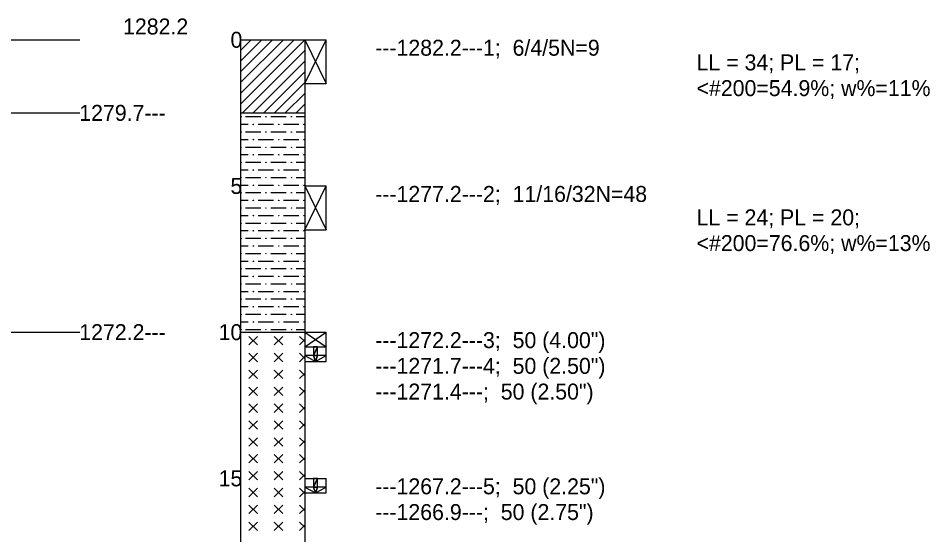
# Model space of a CAD drawing. Extents: x 2150161.5 to 2150203.1, y 143779.5 to 143868.5.
# Drawn here: x 2150174.63 to 2150181.72, y 143825.26 to 143829.28 of the extents above; entities that cross this region are included whole.
import ezdxf

# ---------------------------------------------------------------- set-up
doc = ezdxf.new("R2010")
doc.units = 0
doc.layers.add('Default', color=7, linetype='Continuous')

msp = doc.modelspace()

# ---------------------------------------------------------------- linework, layer by layer
at = {"layer": 'Default'}
for points in [[(2150170.9397, 143829.1095), (2150175.1064, 143829.1095)], [(2150176.3564, 143829.0262), (2150176.4397, 143829.1095)], [(2150176.3564, 143828.9428), (2150176.523, 143829.1095)], [(2150176.3564, 143828.8595), (2150176.6064, 143829.1095)], [(2150176.3564, 143828.7762), (2150176.6897, 143829.1095)], [(2150176.3564, 143828.6928), (2150176.773, 143829.1095)], [(2150176.3564, 143828.6095), (2150176.8564, 143829.1095)], [(2150176.3564, 143829.1095), (2150176.3564, 143816.9504)], [(2150176.3564, 143829.1095), (2150176.8564, 143829.1095)], [(2150176.8564, 143829.1095), (2150177.023, 143828.7686)], [(2150176.8564, 143828.7686), (2150177.023, 143829.1095)], [(2150176.8564, 143829.1095), (2150177.023, 143829.1095)], [(2150176.8564, 143829.1095), (2150176.8564, 143816.9504)], [(2150177.023, 143828.7686), (2150177.023, 143829.1095)], [(2150176.3715, 143828.5413), (2150176.8564, 143829.0262)], [(2150176.4548, 143828.5413), (2150176.8564, 143828.9428)], [(2150176.5382, 143828.5413), (2150176.8564, 143828.8595)], [(2150176.6215, 143828.5413), (2150176.8564, 143828.7762)], [(2150176.8564, 143828.7686), (2150177.023, 143828.7686)], [(2150176.7048, 143828.5413), (2150176.8564, 143828.6928)], [(2150176.7882, 143828.5413), (2150176.8564, 143828.6095)], [(2150170.9397, 143828.5413), (2150175.1064, 143828.5413)], [(2150176.3564, 143828.5413), (2150176.8564, 143828.5413)], [(2150176.3564, 143828.5118), (2150176.3603, 143828.5118), (2150176.3603, 143828.5079), (2150176.3564, 143828.5118)], [(2150176.3957, 143828.5118), (2150176.5138, 143828.5118)], [(2150176.5532, 143828.5118), (2150176.5571, 143828.5118), (2150176.5532, 143828.5079), (2150176.5532, 143828.5118)], [(2150176.5926, 143828.5118), (2150176.7107, 143828.5118)], [(2150176.7501, 143828.5118), (2150176.754, 143828.5118), (2150176.754, 143828.5079), (2150176.7501, 143828.5118)], [(2150176.7894, 143828.5118), (2150176.8564, 143828.5118)], [(2150176.3564, 143828.4527), (2150176.4154, 143828.4527)], [(2150176.4548, 143828.4527), (2150176.4587, 143828.4527), (2150176.4548, 143828.4488), (2150176.4548, 143828.4527)], [(2150176.4942, 143828.4527), (2150176.6123, 143828.4527)], [(2150176.6516, 143828.4527), (2150176.6556, 143828.4527), (2150176.6556, 143828.4488), (2150176.6516, 143828.4527)], [(2150176.691, 143828.4527), (2150176.7501, 143828.4527)], [(2150176.7501, 143828.4527), (2150176.8091, 143828.4527)], [(2150176.8485, 143828.4527), (2150176.8524, 143828.4527), (2150176.8485, 143828.4488), (2150176.8485, 143828.4527)], [(2150176.3564, 143828.3937), (2150176.3603, 143828.3937), (2150176.3603, 143828.3898), (2150176.3564, 143828.3937)], [(2150176.3957, 143828.3937), (2150176.5138, 143828.3937)], [(2150176.5532, 143828.3937), (2150176.5571, 143828.3937), (2150176.5532, 143828.3898), (2150176.5532, 143828.3937)], [(2150176.5926, 143828.3937), (2150176.7107, 143828.3937)], [(2150176.7501, 143828.3937), (2150176.754, 143828.3937), (2150176.754, 143828.3898), (2150176.7501, 143828.3937)], [(2150176.7894, 143828.3937), (2150176.8564, 143828.3937)], [(2150176.3564, 143828.3346), (2150176.4154, 143828.3346)], [(2150176.4548, 143828.3346), (2150176.4587, 143828.3346), (2150176.4548, 143828.3307), (2150176.4548, 143828.3346)], [(2150176.4942, 143828.3346), (2150176.6123, 143828.3346)], [(2150176.6516, 143828.3346), (2150176.6556, 143828.3346), (2150176.6556, 143828.3307), (2150176.6516, 143828.3346)], [(2150176.691, 143828.3346), (2150176.7501, 143828.3346)], [(2150176.7501, 143828.3346), (2150176.8091, 143828.3346)], [(2150176.8485, 143828.3346), (2150176.8524, 143828.3346), (2150176.8485, 143828.3307), (2150176.8485, 143828.3346)], [(2150176.3564, 143828.2756), (2150176.3603, 143828.2756), (2150176.3603, 143828.2716), (2150176.3564, 143828.2756)], [(2150176.3564, 143828.2165), (2150176.4154, 143828.2165)], [(2150176.3957, 143828.2756), (2150176.5138, 143828.2756)], [(2150176.4548, 143828.2165), (2150176.4587, 143828.2165), (2150176.4548, 143828.2126), (2150176.4548, 143828.2165)], [(2150176.4942, 143828.2165), (2150176.6123, 143828.2165)], [(2150176.5532, 143828.2756), (2150176.5571, 143828.2756), (2150176.5532, 143828.2716), (2150176.5532, 143828.2756)], [(2150176.5926, 143828.2756), (2150176.7107, 143828.2756)], [(2150176.6516, 143828.2165), (2150176.6556, 143828.2165), (2150176.6556, 143828.2126), (2150176.6516, 143828.2165)], [(2150176.691, 143828.2165), (2150176.7501, 143828.2165)], [(2150176.7501, 143828.2756), (2150176.754, 143828.2756), (2150176.754, 143828.2716), (2150176.7501, 143828.2756)], [(2150176.7501, 143828.2165), (2150176.8091, 143828.2165)], [(2150176.7894, 143828.2756), (2150176.8564, 143828.2756)], [(2150176.8485, 143828.2165), (2150176.8524, 143828.2165), (2150176.8485, 143828.2126), (2150176.8485, 143828.2165)], [(2150176.3564, 143828.1575), (2150176.3603, 143828.1575), (2150176.3603, 143828.1535), (2150176.3564, 143828.1575)], [(2150176.3957, 143828.1575), (2150176.5138, 143828.1575)], [(2150176.5532, 143828.1575), (2150176.5571, 143828.1575), (2150176.5532, 143828.1535), (2150176.5532, 143828.1575)], [(2150176.5926, 143828.1575), (2150176.7107, 143828.1575)], [(2150176.7501, 143828.1575), (2150176.754, 143828.1575), (2150176.754, 143828.1535), (2150176.7501, 143828.1575)], [(2150176.7894, 143828.1575), (2150176.8564, 143828.1575)], [(2150176.3564, 143828.0984), (2150176.4154, 143828.0984)], [(2150176.4548, 143828.0984), (2150176.4587, 143828.0984), (2150176.4548, 143828.0945), (2150176.4548, 143828.0984)], [(2150176.4942, 143828.0984), (2150176.6123, 143828.0984)], [(2150176.6516, 143828.0984), (2150176.6556, 143828.0984), (2150176.6556, 143828.0945), (2150176.6516, 143828.0984)], [(2150176.691, 143828.0984), (2150176.7501, 143828.0984)], [(2150176.7501, 143828.0984), (2150176.8091, 143828.0984)], [(2150176.8485, 143828.0984), (2150176.8524, 143828.0984), (2150176.8485, 143828.0945), (2150176.8485, 143828.0984)], [(2150176.3564, 143828.0394), (2150176.3603, 143828.0394), (2150176.3603, 143828.0354), (2150176.3564, 143828.0394)], [(2150176.3957, 143828.0394), (2150176.5138, 143828.0394)], [(2150176.5532, 143828.0394), (2150176.5571, 143828.0394), (2150176.5532, 143828.0354), (2150176.5532, 143828.0394)], [(2150176.5926, 143828.0394), (2150176.7107, 143828.0394)], [(2150176.7501, 143828.0394), (2150176.754, 143828.0394), (2150176.754, 143828.0354), (2150176.7501, 143828.0394)], [(2150176.7894, 143828.0394), (2150176.8564, 143828.0394)], [(2150176.3564, 143827.9803), (2150176.4154, 143827.9803)], [(2150176.4548, 143827.9803), (2150176.4587, 143827.9803), (2150176.4548, 143827.9764), (2150176.4548, 143827.9803)], [(2150176.4942, 143827.9803), (2150176.6123, 143827.9803)], [(2150176.6516, 143827.9803), (2150176.6556, 143827.9803), (2150176.6556, 143827.9764), (2150176.6516, 143827.9803)], [(2150176.691, 143827.9803), (2150176.7501, 143827.9803)], [(2150176.7501, 143827.9803), (2150176.8091, 143827.9803)], [(2150176.8485, 143827.9803), (2150176.8524, 143827.9803), (2150176.8485, 143827.9764), (2150176.8485, 143827.9803)], [(2150176.8564, 143827.9731), (2150177.023, 143827.6322)], [(2150176.8564, 143827.6322), (2150177.023, 143827.9731)], [(2150176.8564, 143827.9731), (2150177.023, 143827.9731)], [(2150177.023, 143827.6322), (2150177.023, 143827.9731)], [(2150176.3564, 143827.9212), (2150176.3603, 143827.9212), (2150176.3603, 143827.9173), (2150176.3564, 143827.9212)], [(2150176.3564, 143827.8622), (2150176.4154, 143827.8622)], [(2150176.3957, 143827.9212), (2150176.5138, 143827.9212)], [(2150176.4548, 143827.8622), (2150176.4587, 143827.8622), (2150176.4548, 143827.8583), (2150176.4548, 143827.8622)], [(2150176.4942, 143827.8622), (2150176.6123, 143827.8622)], [(2150176.5532, 143827.9212), (2150176.5571, 143827.9212), (2150176.5532, 143827.9173), (2150176.5532, 143827.9212)], [(2150176.5926, 143827.9212), (2150176.7107, 143827.9212)], [(2150176.6516, 143827.8622), (2150176.6556, 143827.8622), (2150176.6556, 143827.8583), (2150176.6516, 143827.8622)], [(2150176.691, 143827.8622), (2150176.7501, 143827.8622)], [(2150176.7501, 143827.9212), (2150176.754, 143827.9212), (2150176.754, 143827.9173), (2150176.7501, 143827.9212)], [(2150176.7501, 143827.8622), (2150176.8091, 143827.8622)], [(2150176.7894, 143827.9212), (2150176.8564, 143827.9212)], [(2150176.8485, 143827.8622), (2150176.8524, 143827.8622), (2150176.8485, 143827.8583), (2150176.8485, 143827.8622)], [(2150176.3564, 143827.8031), (2150176.3603, 143827.8031), (2150176.3603, 143827.7992), (2150176.3564, 143827.8031)], [(2150176.3957, 143827.8031), (2150176.5138, 143827.8031)], [(2150176.5532, 143827.8031), (2150176.5571, 143827.8031), (2150176.5532, 143827.7992), (2150176.5532, 143827.8031)], [(2150176.5926, 143827.8031), (2150176.7107, 143827.8031)], [(2150176.7501, 143827.8031), (2150176.754, 143827.8031), (2150176.754, 143827.7992), (2150176.7501, 143827.8031)], [(2150176.7894, 143827.8031), (2150176.8564, 143827.8031)], [(2150176.3564, 143827.7441), (2150176.4154, 143827.7441)], [(2150176.4548, 143827.7441), (2150176.4587, 143827.7441), (2150176.4548, 143827.7401), (2150176.4548, 143827.7441)], [(2150176.4942, 143827.7441), (2150176.6123, 143827.7441)], [(2150176.6516, 143827.7441), (2150176.6556, 143827.7441), (2150176.6556, 143827.7401), (2150176.6516, 143827.7441)], [(2150176.691, 143827.7441), (2150176.7501, 143827.7441)], [(2150176.7501, 143827.7441), (2150176.8091, 143827.7441)], [(2150176.8485, 143827.7441), (2150176.8524, 143827.7441), (2150176.8485, 143827.7401), (2150176.8485, 143827.7441)], [(2150176.3564, 143827.685), (2150176.3603, 143827.685), (2150176.3603, 143827.6811), (2150176.3564, 143827.685)], [(2150176.3957, 143827.685), (2150176.5138, 143827.685)], [(2150176.5532, 143827.685), (2150176.5571, 143827.685), (2150176.5532, 143827.6811), (2150176.5532, 143827.685)], [(2150176.5926, 143827.685), (2150176.7107, 143827.685)], [(2150176.7501, 143827.685), (2150176.754, 143827.685), (2150176.754, 143827.6811), (2150176.7501, 143827.685)], [(2150176.7894, 143827.685), (2150176.8564, 143827.685)], [(2150176.3564, 143827.626), (2150176.4154, 143827.626)], [(2150176.4548, 143827.626), (2150176.4587, 143827.626), (2150176.4548, 143827.622), (2150176.4548, 143827.626)], [(2150176.4942, 143827.626), (2150176.6123, 143827.626)], [(2150176.6516, 143827.626), (2150176.6556, 143827.626), (2150176.6556, 143827.622), (2150176.6516, 143827.626)], [(2150176.691, 143827.626), (2150176.7501, 143827.626)], [(2150176.7501, 143827.626), (2150176.8091, 143827.626)], [(2150176.8485, 143827.626), (2150176.8524, 143827.626), (2150176.8485, 143827.622), (2150176.8485, 143827.626)], [(2150176.8564, 143827.6322), (2150177.023, 143827.6322)], [(2150176.3564, 143827.5669), (2150176.3603, 143827.5669), (2150176.3603, 143827.563), (2150176.3564, 143827.5669)], [(2150176.3564, 143827.5079), (2150176.4154, 143827.5079)], [(2150176.3957, 143827.5669), (2150176.5138, 143827.5669)], [(2150176.4548, 143827.5079), (2150176.4587, 143827.5079), (2150176.4548, 143827.5039), (2150176.4548, 143827.5079)], [(2150176.4942, 143827.5079), (2150176.6123, 143827.5079)], [(2150176.5532, 143827.5669), (2150176.5571, 143827.5669), (2150176.5532, 143827.563), (2150176.5532, 143827.5669)], [(2150176.5926, 143827.5669), (2150176.7107, 143827.5669)], [(2150176.6516, 143827.5079), (2150176.6556, 143827.5079), (2150176.6556, 143827.5039), (2150176.6516, 143827.5079)], [(2150176.691, 143827.5079), (2150176.7501, 143827.5079)], [(2150176.7501, 143827.5669), (2150176.754, 143827.5669), (2150176.754, 143827.563), (2150176.7501, 143827.5669)], [(2150176.7501, 143827.5079), (2150176.8091, 143827.5079)], [(2150176.7894, 143827.5669), (2150176.8564, 143827.5669)], [(2150176.8485, 143827.5079), (2150176.8524, 143827.5079), (2150176.8485, 143827.5039), (2150176.8485, 143827.5079)], [(2150176.3564, 143827.4488), (2150176.3603, 143827.4488), (2150176.3603, 143827.4449), (2150176.3564, 143827.4488)], [(2150176.3957, 143827.4488), (2150176.5138, 143827.4488)], [(2150176.5532, 143827.4488), (2150176.5571, 143827.4488), (2150176.5532, 143827.4449), (2150176.5532, 143827.4488)], [(2150176.5926, 143827.4488), (2150176.7107, 143827.4488)], [(2150176.7501, 143827.4488), (2150176.754, 143827.4488), (2150176.754, 143827.4449), (2150176.7501, 143827.4488)], [(2150176.7894, 143827.4488), (2150176.8564, 143827.4488)], [(2150176.3564, 143827.3898), (2150176.4154, 143827.3898)], [(2150176.4548, 143827.3898), (2150176.4587, 143827.3898), (2150176.4548, 143827.3858), (2150176.4548, 143827.3898)], [(2150176.4942, 143827.3898), (2150176.6123, 143827.3898)], [(2150176.6516, 143827.3898), (2150176.6556, 143827.3898), (2150176.6556, 143827.3858), (2150176.6516, 143827.3898)], [(2150176.691, 143827.3898), (2150176.7501, 143827.3898)], [(2150176.7501, 143827.3898), (2150176.8091, 143827.3898)], [(2150176.8485, 143827.3898), (2150176.8524, 143827.3898), (2150176.8485, 143827.3858), (2150176.8485, 143827.3898)], [(2150176.3564, 143827.3307), (2150176.3603, 143827.3307), (2150176.3603, 143827.3268), (2150176.3564, 143827.3307)], [(2150176.3957, 143827.3307), (2150176.5138, 143827.3307)], [(2150176.5532, 143827.3307), (2150176.5571, 143827.3307), (2150176.5532, 143827.3268), (2150176.5532, 143827.3307)], [(2150176.5926, 143827.3307), (2150176.7107, 143827.3307)], [(2150176.7501, 143827.3307), (2150176.754, 143827.3307), (2150176.754, 143827.3268), (2150176.7501, 143827.3307)], [(2150176.7894, 143827.3307), (2150176.8564, 143827.3307)], [(2150176.3564, 143827.2716), (2150176.4154, 143827.2716)], [(2150176.4548, 143827.2716), (2150176.4587, 143827.2716), (2150176.4548, 143827.2677), (2150176.4548, 143827.2716)], [(2150176.4942, 143827.2716), (2150176.6123, 143827.2716)], [(2150176.6516, 143827.2716), (2150176.6556, 143827.2716), (2150176.6556, 143827.2677), (2150176.6516, 143827.2716)], [(2150176.691, 143827.2716), (2150176.7501, 143827.2716)], [(2150176.7501, 143827.2716), (2150176.8091, 143827.2716)], [(2150176.8485, 143827.2716), (2150176.8524, 143827.2716), (2150176.8485, 143827.2677), (2150176.8485, 143827.2716)], [(2150176.3564, 143827.2126), (2150176.3603, 143827.2126), (2150176.3603, 143827.2087), (2150176.3564, 143827.2126)], [(2150176.3564, 143827.1535), (2150176.4154, 143827.1535)], [(2150176.3957, 143827.2126), (2150176.5138, 143827.2126)], [(2150176.4548, 143827.1535), (2150176.4587, 143827.1535), (2150176.4548, 143827.1496), (2150176.4548, 143827.1535)], [(2150176.4942, 143827.1535), (2150176.6123, 143827.1535)], [(2150176.5532, 143827.2126), (2150176.5571, 143827.2126), (2150176.5532, 143827.2087), (2150176.5532, 143827.2126)], [(2150176.5926, 143827.2126), (2150176.7107, 143827.2126)], [(2150176.6516, 143827.1535), (2150176.6556, 143827.1535), (2150176.6556, 143827.1496), (2150176.6516, 143827.1535)], [(2150176.691, 143827.1535), (2150176.7501, 143827.1535)], [(2150176.7501, 143827.2126), (2150176.754, 143827.2126), (2150176.754, 143827.2087), (2150176.7501, 143827.2126)], [(2150176.7501, 143827.1535), (2150176.8091, 143827.1535)], [(2150176.7894, 143827.2126), (2150176.8564, 143827.2126)], [(2150176.8485, 143827.1535), (2150176.8524, 143827.1535), (2150176.8485, 143827.1496), (2150176.8485, 143827.1535)], [(2150176.3564, 143827.0945), (2150176.3603, 143827.0945), (2150176.3603, 143827.0905), (2150176.3564, 143827.0945)], [(2150176.3957, 143827.0945), (2150176.5138, 143827.0945)], [(2150176.5532, 143827.0945), (2150176.5571, 143827.0945), (2150176.5532, 143827.0905), (2150176.5532, 143827.0945)], [(2150176.5926, 143827.0945), (2150176.7107, 143827.0945)], [(2150176.7501, 143827.0945), (2150176.754, 143827.0945), (2150176.754, 143827.0905), (2150176.7501, 143827.0945)], [(2150176.7894, 143827.0945), (2150176.8564, 143827.0945)], [(2150176.3564, 143827.0354), (2150176.4154, 143827.0354)], [(2150176.4548, 143827.0354), (2150176.4587, 143827.0354), (2150176.4548, 143827.0315), (2150176.4548, 143827.0354)], [(2150176.4942, 143827.0354), (2150176.6123, 143827.0354)], [(2150176.6516, 143827.0354), (2150176.6556, 143827.0354), (2150176.6556, 143827.0315), (2150176.6516, 143827.0354)], [(2150176.691, 143827.0354), (2150176.7501, 143827.0354)], [(2150176.7501, 143827.0354), (2150176.8091, 143827.0354)], [(2150176.8485, 143827.0354), (2150176.8524, 143827.0354), (2150176.8485, 143827.0315), (2150176.8485, 143827.0354)], [(2150176.3564, 143826.9764), (2150176.3603, 143826.9764), (2150176.3603, 143826.9724), (2150176.3564, 143826.9764)], [(2150176.3957, 143826.9764), (2150176.5138, 143826.9764)], [(2150176.5532, 143826.9764), (2150176.5571, 143826.9764), (2150176.5532, 143826.9724), (2150176.5532, 143826.9764)], [(2150176.5926, 143826.9764), (2150176.7107, 143826.9764)], [(2150176.7501, 143826.9764), (2150176.754, 143826.9764), (2150176.754, 143826.9724), (2150176.7501, 143826.9764)], [(2150176.7894, 143826.9764), (2150176.8564, 143826.9764)], [(2150176.3564, 143826.9173), (2150176.4154, 143826.9173)], [(2150176.4548, 143826.9173), (2150176.4587, 143826.9173), (2150176.4548, 143826.9134), (2150176.4548, 143826.9173)], [(2150176.4942, 143826.9173), (2150176.6123, 143826.9173)], [(2150176.6516, 143826.9173), (2150176.6556, 143826.9173), (2150176.6556, 143826.9134), (2150176.6516, 143826.9173)], [(2150176.691, 143826.9173), (2150176.7501, 143826.9173)], [(2150176.7501, 143826.9173), (2150176.8091, 143826.9173)], [(2150176.8485, 143826.9173), (2150176.8524, 143826.9173), (2150176.8485, 143826.9134), (2150176.8485, 143826.9173)], [(2150170.9397, 143826.8368), (2150175.1064, 143826.8368)], [(2150176.3564, 143826.8583), (2150176.3603, 143826.8583), (2150176.3603, 143826.8543), (2150176.3564, 143826.8583)], [(2150176.3564, 143826.8368), (2150176.8564, 143826.8368)], [(2150176.3957, 143826.8583), (2150176.5138, 143826.8583)], [(2150176.4876, 143826.804), (2150176.422, 143826.7384)], [(2150176.422, 143826.804), (2150176.4876, 143826.7384)], [(2150176.5532, 143826.8583), (2150176.5571, 143826.8583), (2150176.5532, 143826.8543), (2150176.5532, 143826.8583)], [(2150176.5926, 143826.8583), (2150176.7107, 143826.8583)], [(2150176.6844, 143826.804), (2150176.6188, 143826.7384)], [(2150176.6188, 143826.804), (2150176.6844, 143826.7384)], [(2150176.7501, 143826.8583), (2150176.754, 143826.8583), (2150176.754, 143826.8543), (2150176.7501, 143826.8583)], [(2150176.7894, 143826.8583), (2150176.8564, 143826.8583)], [(2150176.8157, 143826.804), (2150176.8564, 143826.7633)], [(2150176.8564, 143826.8368), (2150177.023, 143826.7231)], [(2150176.8564, 143826.7231), (2150177.023, 143826.8368)], [(2150176.8564, 143826.8368), (2150177.023, 143826.8368)], [(2150177.023, 143826.7231), (2150177.023, 143826.8368)], [(2150176.8564, 143826.779), (2150176.8157, 143826.7384)], [(2150176.8564, 143826.7231), (2150177.023, 143826.7231)], [(2150176.8564, 143826.7231), (2150177.023, 143826.7231)], [(2150177.023, 143826.6095), (2150177.023, 143826.7231)], [(2150176.4876, 143826.6727), (2150176.422, 143826.6071)], [(2150176.422, 143826.6727), (2150176.4876, 143826.6071)], [(2150176.6844, 143826.6727), (2150176.6188, 143826.6071)], [(2150176.6188, 143826.6727), (2150176.6844, 143826.6071)], [(2150176.8157, 143826.6727), (2150176.8564, 143826.6321)], [(2150176.8564, 143826.6478), (2150176.8157, 143826.6071)], [(2150176.8564, 143826.6095), (2150177.023, 143826.6095)], [(2150176.4876, 143826.5415), (2150176.422, 143826.4759)], [(2150176.422, 143826.5415), (2150176.4876, 143826.4759)], [(2150176.6844, 143826.5415), (2150176.6188, 143826.4759)], [(2150176.6188, 143826.5415), (2150176.6844, 143826.4759)], [(2150176.8157, 143826.5415), (2150176.8564, 143826.5008)], [(2150176.8564, 143826.5166), (2150176.8157, 143826.4759)], [(2150176.4876, 143826.4103), (2150176.422, 143826.3447)], [(2150176.422, 143826.4103), (2150176.4876, 143826.3447)], [(2150176.6844, 143826.4103), (2150176.6188, 143826.3447)], [(2150176.6188, 143826.4103), (2150176.6844, 143826.3447)], [(2150176.8157, 143826.4103), (2150176.8564, 143826.3696)], [(2150176.8564, 143826.3853), (2150176.8157, 143826.3447)], [(2150176.4876, 143826.279), (2150176.422, 143826.2134)], [(2150176.422, 143826.279), (2150176.4876, 143826.2134)], [(2150176.6844, 143826.279), (2150176.6188, 143826.2134)], [(2150176.6188, 143826.279), (2150176.6844, 143826.2134)], [(2150176.8157, 143826.279), (2150176.8564, 143826.2384)], [(2150176.8564, 143826.2541), (2150176.8157, 143826.2134)], [(2150176.4876, 143826.1478), (2150176.422, 143826.0822)], [(2150176.422, 143826.1478), (2150176.4876, 143826.0822)], [(2150176.6844, 143826.1478), (2150176.6188, 143826.0822)], [(2150176.6188, 143826.1478), (2150176.6844, 143826.0822)], [(2150176.8157, 143826.1478), (2150176.8564, 143826.1071)], [(2150176.8564, 143826.1229), (2150176.8157, 143826.0822)], [(2150176.4876, 143826.0166), (2150176.422, 143825.951)], [(2150176.422, 143826.0166), (2150176.4876, 143825.951)], [(2150176.6844, 143826.0166), (2150176.6188, 143825.951)], [(2150176.6188, 143826.0166), (2150176.6844, 143825.951)], [(2150176.8157, 143826.0166), (2150176.8564, 143825.9759)], [(2150176.8564, 143825.9916), (2150176.8157, 143825.951)], [(2150176.4876, 143825.8853), (2150176.422, 143825.8197)], [(2150176.422, 143825.8853), (2150176.4876, 143825.8197)], [(2150176.6844, 143825.8853), (2150176.6188, 143825.8197)], [(2150176.6188, 143825.8853), (2150176.6844, 143825.8197)], [(2150176.8157, 143825.8853), (2150176.8564, 143825.8447)], [(2150176.8564, 143825.8604), (2150176.8157, 143825.8197)], [(2150176.4876, 143825.7541), (2150176.422, 143825.6885)], [(2150176.422, 143825.7541), (2150176.4876, 143825.6885)], [(2150176.6844, 143825.7541), (2150176.6188, 143825.6885)], [(2150176.6188, 143825.7541), (2150176.6844, 143825.6885)], [(2150176.8157, 143825.7541), (2150176.8564, 143825.7134)], [(2150176.8564, 143825.7292), (2150176.8157, 143825.6885)], [(2150176.8564, 143825.7004), (2150177.023, 143825.7004)], [(2150177.023, 143825.5868), (2150177.023, 143825.7004)], [(2150176.4876, 143825.6229), (2150176.422, 143825.5573)], [(2150176.422, 143825.6229), (2150176.4876, 143825.5573)], [(2150176.6844, 143825.6229), (2150176.6188, 143825.5573)], [(2150176.6188, 143825.6229), (2150176.6844, 143825.5573)], [(2150176.8157, 143825.6229), (2150176.8564, 143825.5822)], [(2150176.8564, 143825.5979), (2150176.8157, 143825.5573)], [(2150176.8564, 143825.5868), (2150177.023, 143825.5868)], [(2150176.4876, 143825.4916), (2150176.422, 143825.426)], [(2150176.422, 143825.4916), (2150176.4876, 143825.426)], [(2150176.6844, 143825.4916), (2150176.6188, 143825.426)], [(2150176.6188, 143825.4916), (2150176.6844, 143825.426)], [(2150176.8157, 143825.4916), (2150176.8564, 143825.451)], [(2150176.8564, 143825.4667), (2150176.8157, 143825.426)], [(2150176.4876, 143825.3604), (2150176.422, 143825.2948)], [(2150176.422, 143825.3604), (2150176.4876, 143825.2948)], [(2150176.6844, 143825.3604), (2150176.6188, 143825.2948)], [(2150176.6188, 143825.3604), (2150176.6844, 143825.2948)], [(2150176.8157, 143825.3604), (2150176.8564, 143825.3197)], [(2150176.8564, 143825.3355), (2150176.8157, 143825.2948)]]:
    msp.add_lwpolyline(points, dxfattribs=at)
for points in [[(2150176.923, 143826.655), (2150176.9564, 143826.655), (2150176.9564, 143826.7231), (2150176.923, 143826.655)], [(2150176.923, 143826.655), (2150176.9564, 143826.7231), (2150176.923, 143826.7231), (2150176.923, 143826.655)], [(2150176.923, 143826.655), (2150176.8564, 143826.655), (2150176.9397, 143826.6095), (2150176.923, 143826.655)], [(2150176.923, 143826.655), (2150176.9397, 143826.6095), (2150176.9564, 143826.655), (2150176.923, 143826.655)], [(2150176.9397, 143826.6095), (2150177.023, 143826.655), (2150176.9564, 143826.655), (2150176.9397, 143826.6095)], [(2150176.923, 143825.6322), (2150176.9564, 143825.6322), (2150176.9564, 143825.7004), (2150176.923, 143825.6322)], [(2150176.923, 143825.6322), (2150176.9564, 143825.7004), (2150176.923, 143825.7004), (2150176.923, 143825.6322)], [(2150176.923, 143825.6322), (2150176.8564, 143825.6322), (2150176.9397, 143825.5868), (2150176.923, 143825.6322)], [(2150176.923, 143825.6322), (2150176.9397, 143825.5868), (2150176.9564, 143825.6322), (2150176.923, 143825.6322)], [(2150176.9397, 143825.5868), (2150177.023, 143825.6322), (2150176.9564, 143825.6322), (2150176.9397, 143825.5868)]]:
    msp.add_lwpolyline(points, close=True, dxfattribs=at)

# ---------------------------------------------------------------- texts
for s, p in [('1282.2', (2150175.4423, 143829.1508)), ('0', (2150176.2781, 143829.0475)), ('---1282.2---1;  6/4/5N=9', (2150177.4044, 143828.9855)), ('LL = 34; PL = 17;', (2150179.9044, 143828.8716)), ('<#200=54.9%; w%=11%', (2150179.9044, 143828.6716)), ('1279.7---', (2150175.1015, 143828.4793)), ('5', (2150176.2781, 143827.9111)), ('---1277.2---2;  11/16/32N=48', (2150177.4044, 143827.8491)), ('LL = 24; PL = 20;', (2150179.9044, 143827.6671)), ('<#200=76.6%; w%=13%', (2150179.9044, 143827.4671)), ('1272.2---', (2150175.1015, 143826.7748)), ('10', (2150176.1859, 143826.7748)), ('---1272.2---3;  50 (4.00")', (2150177.4044, 143826.7128)), ('---1271.7---4;  50 (2.50")', (2150177.4044, 143826.5128)), ('---1271.4---;  50 (2.50")', (2150177.4044, 143826.3128)), ('15', (2150176.1859, 143825.6384)), ('---1267.2---5;  50 (2.25")', (2150177.4044, 143825.5764)), ('---1266.9---;  50 (2.75")', (2150177.4044, 143825.3764))]:
    msp.add_text(s, height=0.124, dxfattribs=at).set_placement(p)

doc.saveas('drawing.dxf')
